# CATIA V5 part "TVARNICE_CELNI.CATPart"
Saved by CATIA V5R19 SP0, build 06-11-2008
Material "Steel": density 7860 kg/m3, Young's modulus 2e+11 Pa, Poisson ratio 0.266, thermal expansion 1.17e-05 1/K
Bounding box of the stored display mesh (mm): x -26 to 70, y -275 to 275, z 0 to 66
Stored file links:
  G:\UTB\Kombinované\Bakalářská práce\Catia\FORMA\TVARNICE_CELNI.CATPart
  G:\UTB\Kombinované\Bakalářská práce\Catia\KONCOVKA.CATPart
  D:\Aplikace\CATIA\Nová složka\win_b64\startup\materials\Catalog.CATMaterial
  G:\UTB\Kombinované\Bakalářská práce\Catia\FORMA_3.0_MODELY\installation space_HMT4.CATPart
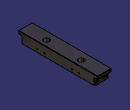
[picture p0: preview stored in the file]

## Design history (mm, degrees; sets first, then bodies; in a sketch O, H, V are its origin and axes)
Solid1: linked copy from another document
Sketch1 on xy-plane, origin (0, 0, 0), H (1, 0, 0), V (0, 1, 0)
  point P1 (22, 0)
  line L1 (-26, 275) -> (-26, -275)
  line L2 (-26, -275) -> (70, -275)
  line L3 (70, -275) -> (70, 275)
  line L4 (70, 275) -> (-26, 275)
  reference intersected line E1 through (0, 0) direction (-1, 0) from zx-plane
  reference intersected line E2 through (0, 0) direction (0, 1) from yz-plane
  distance L3 L1 = 96
  distance L4 L2 = 550
  distance L1 E2 = 26
  vertical: L1 V, L3 V
  horizontal: L2 H, L4 H
  equidistance: L1 L3 P1, L2 L4 P1
  coincidence: P1 E1
Pad1: profile Sketch1, direction (0, 0, 1), length 66
Set1 "ROZVODNE_KANALY"
  Sketch2 on xy-plane, origin (0, 0, 0), H (1, 0, 0), V (0, 1, 0)
    line L1 (30, 60) -> (0, 60)
    point P2 (0, 60)
    line L2 (30, 180) -> (0, 180)
    point P4 (0, 180)
    reference intersected line E1 through (0, 0) direction (0, 1) from yz-plane
    reference intersected line E2 through (0, 0) direction (0, 1) from yz-plane
    line L3 (30, 60) -> (30, 180)
    reference intersected line E3 through (0, 0) direction (-1, 0) from zx-plane
    reference intersected line E4 through (0, 120) direction (-1, 0) from Plane2
    reference intersected line E5 through (0, 0) direction (0, 1) from yz-plane
    distance L1 E3 = 60
    distance L3 E5 = 30
    horizontal: L1 H, L2 H
    coincidence: P2 E1, P4 E2
    vertical: L3 V
    symmetry: L2 L1 E4
  Plane1: type Offset, Offset 60, RefPlane Plane5
  Plane2: type Offset, Offset 60, RefPlane Plane5, reversed
  Plane3: type Offset, Offset 30, RefPlane yz-plane
  Plane4: type Offset, Offset 25, RefPlane Plane3
Body1 (main body)
  Sketch3 on yz-plane, origin (0, 0, 0), H (0, 1, 0), V (0, 0, 1)
    point P1 (275, 46)
    line L1 (275, 46) -> (255, 46)
    line L2 (255, 46) -> (255, 0)
    line L3 (255, 0) -> (275, 0)
    line L4 (275, 0) -> (275, 46)
    point P2 (255, 46)
    point P3 (255, 0)
    point P4 (275, 0)
    reference projected line E1 (-400, 0) -> (400, 0) from edge [start face of Pad1 | face of Pad1 from Sketch1.L3]
    reference projected line E2 (275, 0) -> (275, 116) from edge [face of Pad1 from Sketch1.L4 | face of Pad1 from Sketch1.L3]
    reference intersected line E3 through (0, 0) direction (0, 1) from zx-plane
    point P7 (-275, 46)
    point P8 (-255, 46)
    point P9 (-255, 0)
    point P10 (-275, 0)
    line L5 (-275, 46) -> (-255, 46)
    line L6 (-255, 46) -> (-255, 0)
    line L7 (-255, 0) -> (-275, 0)
    line L8 (-275, 0) -> (-275, 46)
    reference projected line E4 (-400, 66) -> (400, 66) from edge [face of Pad1 from Sketch1.L3 | end face of Pad1]
    distance L2 L4 = 20
    distance L1 E4 = 20
    horizontal: L1 H, L3 H
    vertical: L2 V, L4 V
    coincidence: L3 E1, L4 E2
    symmetry: P1 P7 E3, P2 P8 E3, P3 P9 E3, P4 P10 E3, L1 L5 E3, L2 L6 E3, L3 L7 E3, L4 L8 E3
  Pocket1: profile Sketch3, direction (-1, 0, 0), through (limit type 3), opposite side through (limit type 3)
  Body2
    RectPattern1: of Solid1, direction 1 instances 8, spacing 60, along Y axis reversed
    Symmetry1: Reference xy-plane, ToTransfor RectPattern1
  Remove1: tool Body2
  Trim1: faces to remove start face of Pad1 (x8)
  Chamfer1: length 5, angle 45, on edge [face of Pad1 from Sketch1.L3 | face of Pocket1 from Sketch3.L6]; edge [face of Pocket1 from Sketch3.L6 | face of Pad1 from Sketch1.L1]; edge [face of Pad1 from Sketch1.L1 | face of Pocket1 from Sketch3.L2]; edge [face of Pad1 from Sketch1.L3 | face of Pad1 from Sketch1.L2]; edge [face of Pad1 from Sketch1.L2 | face of Pad1 from Sketch1.L1]; edge [face of Pad1 from Sketch1.L1 | face of Pad1 from Sketch1.L4]; edge [face of Pad1 from Sketch1.L4 | face of Pad1 from Sketch1.L3]; edge [face of Pocket1 from Sketch3.L2 | face of Pad1 from Sketch1.L3]
  Chamfer2: length 2, angle 45, on end face of Pad1; edge [face of Pad1 from Sketch1.L3 | face of Pocket1 from Sketch3.L1]; edge [face of Pocket1 from Sketch3.L1 | face of Chamfer1] (x2); edge [face of Pocket1 from Sketch3.L1 | face of Pad1 from Sketch1.L4]; edge [face of Pad1 from Sketch1.L1 | face of Pocket1 from Sketch3.L1]; edge [face of Pad1 from Sketch1.L3 | face of Pocket1 from Sketch3.L5]; edge [face of Pocket1 from Sketch3.L5 | face of Chamfer1] (x2); edge [face of Pad1 from Sketch1.L2 | face of Pocket1 from Sketch3.L5]; edge [face of Pad1 from Sketch1.L1 | face of Pocket1 from Sketch3.L5]
  Plane5: type Offset, Offset 180, RefPlane zx-plane
  Sketch4 on yz-plane, origin (0, 0, 0), H (0, 1, 0), V (0, 0, 1)
    arc A1 centre (180, 3) radius 3 from (182.9886, 3.2615) to (177.0114, 3.2615) ccw
    point P1 (180, 3)
    line L1 (182.9886, 3.2615) -> (183.2739, 0)
    point P2 (183.2739, 0)
    line L2 (183.2739, 0) -> (176.7261, 0)
    point P3 (176.7261, 0)
    line L3 (176.7261, 0) -> (177.0114, 3.2615)
    reference intersected line E1 through (0, 0) direction (-1, 0) from xy-plane
    reference intersected line E2 through (180, 0) direction (0, 1) from Plane5
    reference intersected line E3 through (180, 0) direction (0, 1) from Plane5
    point P4 (177.0114, 3.2615)
    point P5 (182.9886, 3.2615)
    reference intersected line E4 through (240, 0) direction (0, 1) from Plane1
    point P9 (296.7261, 0)
    point P10 (303.2739, 0)
    point P11 (302.9886, 3.2615)
    point P12 (297.0114, 3.2615)
    arc A2 centre (300, 3) radius 3 from (297.0114, 3.2615) to (302.9886, 3.2615) cw
    line L4 (297.0114, 3.2615) -> (296.7261, 0)
    line L5 (296.7261, 0) -> (303.2739, 0)
    line L6 (303.2739, 0) -> (302.9886, 3.2615)
    reference intersected line E5 through (120, 0) direction (0, 1) from Plane2
    point P16 (56.7261, 0)
    point P17 (63.2739, 0)
    point P18 (62.9886, 3.2615)
    point P19 (57.0114, 3.2615)
    arc A3 centre (60, 3) radius 3 from (57.0114, 3.2615) to (62.9886, 3.2615) cw
    line L7 (57.0114, 3.2615) -> (56.7261, 0)
    line L8 (56.7261, 0) -> (63.2739, 0)
    line L9 (63.2739, 0) -> (62.9886, 3.2615)
    radius A1 = 3
    angle L1 L2 = 85
    horizontal: L2 H
    coincidence: L2 E1, P1 E3
    symmetry: L3 L1 E2, P2 P9 E4, P3 P10 E4, P4 P11 E4, P5 P12 E4, A1 A2 E4, L1 L4 E4, L2 L5 E4, L3 L6 E4, P2 P16 E5, P3 P17 E5, P4 P18 E5, P5 P19 E5, A1 A3 E5, L1 L7 E5, L2 L8 E5, L3 L9 E5
    tangency: A1 L3, A1 L1, A1 L2
  Pocket2: profile Sketch4, direction (1, 0, 0), length 30, opposite side length 3
  Sketch5 on Plane5, origin (0, 180, 0), H (-1, 0, 0), V (0, 0, 1)
    arc A1 centre (-30, 3) radius 3 from (-27.0114, 3.2615) to (-32.9886, 3.2615) ccw
    point P1 (-30, 3)
    reference intersected line E1 through (-30, 0) direction (0, -1) from Plane3
    reference intersected line E2 through (0, 0) direction (-1, 0) from xy-plane
    line L1 (-32.9886, 3.2615) -> (-33.2739, 0)
    line L2 (-33.2739, 0) -> (-26.7261, 0)
    line L3 (-26.7261, 0) -> (-27.0114, 3.2615)
    reference intersected line E3 through (0, 0) direction (-1, 0) from xy-plane
    reference intersected line E4 through (-30, 0) direction (0, -1) from Plane3
    radius A1 = 3
    angle L3 L2 = 85
    coincidence: P1 E1, L2 E3
    tangency: A1 E2, L3 A1, L1 A1
    horizontal: L2 H
    symmetry: L3 L1 E4
  Pocket3: profile Sketch5, direction (0, -1, 0), length 130, opposite side length 10
  Fillet1: radius 3, on edge [face of Pocket3 from Sketch5.A1 | end face of Pocket3]; edge [face of Pocket2 from Sketch4.A1 | start face of Pocket2]; edge [face of Pocket2 from Sketch4.A3 | start face of Pocket2]; edge [start face of Pocket3 | face of Pocket3 from Sketch5.A1]; edge [face of Pocket3 from Sketch5.A1 | face of Pocket2 from Sketch4.A3]; edge [face of Pocket3 from Sketch5.A1 | face of Pocket2 from Sketch4.A1]
  Intersect1: ToIntersect1 zx-plane, ToIntersect2 yz-plane
  Sketch6 on face of Pocket1 from Sketch3.L2, origin (54.5146, 255, 17.6418), H (1, 0, 0), V (0, 0, -1)
    point P1 (0.4854, -2.3582)
    reference projected line E1 (25.4854, 17.6418) -> (-134.5146, 17.6418) from edge [start face of Pad1 | face of Pocket1 from Sketch3.L2]
    reference projected line E2 (10.4854, 17.6418) -> (10.4854, -58.3582) from edge [face of Pocket1 from Sketch3.L2 | face of Chamfer1]
    distance P1 E1 = 20
    distance P1 E2 = 10
  Hole1: placed by Sketch6, at (55, 255, 20) direction (0, -1, 0), diameter 8, depth 160, V-bottom angle 120
  Sketch7 on face of Pad1 from Sketch1.L3, origin (70, 205.1332, 34.9028), H (0, 1, 0), V (0, 0, 1)
    point P1 (-110.1332, -14.9028)
    reference projected line E1 (49.8668, -34.9028) -> (49.8668, 41.0972) from edge [face of Pocket1 from Sketch3.L2 | face of Chamfer1]
    reference projected line E2 (-605.1332, -34.9028) -> (194.8668, -34.9028) from edge [start face of Pad1 | face of Pad1 from Sketch1.L3]
    distance P1 E1 = 160
    distance P1 E2 = 20
  Hole2: placed by Sketch7, at (70, 95, 20) direction (-1, 0, 0), diameter 8, depth 63, V-bottom angle 120
  Mirror1: of Hole2, about zx-plane
  Mirror2: of Hole1, about zx-plane
  Sketch8 on face of Pad1 from Sketch1.L1, origin (-26, -340.4239, 34.4779), H (0, 1, 0), V (0, 0, -1)
    point P1 (110.4239, 14.4779)
    reference projected line E1 (740.4239, 34.4779) -> (-59.5761, 34.4779) from edge [start face of Pad1 | face of Pad1 from Sketch1.L1]
    reference projected line E2 (85.4239, 34.4779) -> (85.4239, -41.5221) from edge [face of Pocket1 from Sketch3.L6 | face of Chamfer1]
    distance P1 E1 = 20
    distance P1 E2 = 25
  Hole3: placed by Sketch8, at (-26, -230, 20) direction (1, 0, 0), diameter 8, depth 81, V-bottom angle 120
  Sketch9 on face of Pocket1 from Sketch3.L2, origin (0.6599, 255, 20.6303), H (1, 0, 0), V (0, 0, 1)
    point P1 (6.3401, -0.6303)
    reference projected line E1 (69.3401, -20.6303) -> (69.3401, 55.3697) from edge [face of Pad1 from Sketch1.L3 | face of Chamfer1]
    reference projected line E2 (79.3401, -20.6303) -> (-80.6599, -20.6303) from edge [face of Pocket1 from Sketch3.L6 | start face of Pad1]
    distance P1 E1 = 63
    distance P1 E2 = 20
  Hole4: placed by Sketch9, at (7, 255, 20) direction (0, -1, 0), diameter 8, through (limit type 3)
  Mirror3: of Hole3, about zx-plane
  Sketch10 on face of Pocket1 from Sketch3.L6, origin (-48.4988, -255, 26.5459), H (1, 0, 0), V (0, 0, 1)
    point P1 (37.4988, -6.5459)
    reference projected line E1 (128.4988, -26.5459) -> (-31.5012, -26.5459) from edge [face of Pocket1 from Sketch3.L6 | start face of Pad1]
    reference intersected line E2 through (48.4988, 0) direction (0, 1) from yz-plane
    distance P1 E1 = 20
    distance P1 E2 = 11
  Hole5: placed by Sketch10, at (-11, -255, 20) direction (0, 1, 0), diameter 8, through (limit type 3)
  Sketch11 on face of Pocket1 from Sketch3.L2, origin (0, 255, 0), H (1, 0, 0), V (0, 0, 1)
    circle A1 centre (-11, 20) radius 5.1
    point P1 (-11, 20)
    circle A2 centre (-11, 20) radius 7
    point P2 (-11, 20)
    circle A3 centre (55, 20) radius 5.1
    point P3 (55, 20)
    circle A4 centre (55, 20) radius 7
    point P4 (55, 20)
    reference projected circle E1 centre (-11, 20) radius 4 from edge [face of Pocket1 from Sketch3.L6 | face of Hole5]
    reference projected circle E2 centre (-11, 20) radius 4 from edge [face of Pocket1 from Sketch3.L6 | face of Hole5]
    reference projected circle E3 centre (55, 20) radius 4 from edge [face of Pocket1 from Sketch3.L6 | face of Mirror2]
    reference projected circle E4 centre (55, 20) radius 4 from edge [face of Pocket1 from Sketch3.L6 | face of Mirror2]
    radius A1 = 5.1
    radius A2 = 7
    radius A3 = 5.1
    radius A4 = 7
    concentricity: P2 E1, P1 E2, P4 E3, P3 E4
  Pocket4: profile Sketch11, direction (0, -1, 0), length 1.2
  Mirror4: of Pocket4, about zx-plane
  Sketch12 on face of Pocket1 from Sketch3.L6, origin (0, -255, 0), H (-1, 0, 0), V (0, 0, 1)
    point P1 (11, 20)
    point P2 (-55, 20)
    reference projected circle E1 centre (-55, 20) radius 4 from edge [face of Pocket1 from Sketch3.L6 | face of Mirror2]
    reference projected circle E2 centre (11, 20) radius 4 from edge [face of Pocket1 from Sketch3.L6 | face of Hole5]
    point P3 (-7, 20)
    reference projected circle E3 centre (-7, 20) radius 4 from edge [face of Hole4 | face of Pocket1 from Sketch3.L2]
    concentricity: P2 E1, P1 E2, P3 E3
  Sketch13 on face of Pocket1 from Sketch3.L6, origin (62, -255, 20), H (1, 0, 0), V (0, 0, 1)
    point P1 (-7, 0)
    reference projected point E1 (-7, 0) from Sketch12.P2
    coincidence: E1 P1
  Hole6: placed by Sketch13, at (55, -255, 20) direction (0, 1, 0), diameter 9, depth 10, V-bottom angle 120
  UserPattern1: of Hole6, copies 3, at the points of Sketch12
  Sketch14 on face of Pocket1 from Sketch3.L2, origin (0, 255, 0), H (1, 0, 0), V (0, 0, 1)
    point P1 (55, 20)
    point P2 (7, 20)
    point P3 (-11, 20)
    reference projected circle E1 centre (-11, 20) radius 4 from edge [face of Hole5 | face of Pocket1 from Sketch3.L2]
    reference projected circle E2 centre (7, 20) radius 4 from edge [face of Hole4 | face of Pocket1 from Sketch3.L2]
    reference projected circle E3 centre (55, 20) radius 4 from edge [face of Hole1 | face of Pocket1 from Sketch3.L2]
    concentricity: P3 E1, P2 E2, P1 E3
  Sketch15 on face of Pocket1 from Sketch3.L2, origin (-44, 255, 20), H (1, 0, 0), V (0, 0, -1)
    point P1 (33, 0)
    reference projected point E1 (33, 0) from Sketch14.P3
    coincidence: E1 P1
  Hole7: placed by Sketch15, at (-11, 255, 20) direction (0, -1, 0), diameter 9, depth 10, V-bottom angle 120
  UserPattern2: of Hole7, copies 3, at the points of Sketch14
  Sketch16 on face of Pad1 from Sketch1.L3, origin (70, 0, 0), H (0, 1, 0), V (0, 0, 1)
    point P1 (-95, 20)
    point P2 (95, 20)
    reference projected circle E1 centre (95, 20) radius 4 from edge [face of Pad1 from Sketch1.L3 | face of Hole2]
    reference projected circle E2 centre (-95, 20) radius 4 from edge [face of Pad1 from Sketch1.L3 | face of Mirror1]
    point P3 (-145, 20)
    reference intersected line E3 through (0, 0) direction (-1, 0) from xy-plane
    distance P3 P2 = 240
    distance P3 E3 = 20
    concentricity: P2 E1, P1 E2
  Sketch17 on face of Pad1 from Sketch1.L3, origin (70, 208, 20), H (0, 1, 0), V (0, 0, 1)
    point P1 (-113, 0)
    reference projected point E1 (-113, 0) from Sketch16.P2
    coincidence: E1 P1
  Hole8: placed by Sketch17, at (70, 95, 20) direction (-1, 0, 0), diameter 9, depth 10, V-bottom angle 120
  UserPattern3: of Hole8, copies 3, at the points of Sketch16
  Sketch18 on face of Pad1 from Sketch1.L1, origin (-26, 0, 0), H (0, -1, 0), V (0, 0, 1)
    point P1 (-230, 20)
    point P2 (230, 20)
    reference projected circle E1 centre (230, 20) radius 4 from edge [face of Pad1 from Sketch1.L1 | face of Hole3]
    reference projected circle E2 centre (-230, 20) radius 4 from edge [face of Pad1 from Sketch1.L1 | face of Mirror3]
    concentricity: P2 E1, P1 E2
  Sketch19 on face of Pad1 from Sketch1.L1, origin (-26, 350, 20), H (0, 1, 0), V (0, 0, -1)
    point P1 (-120, 0)
    reference projected point E1 (-120, 0) from Sketch18.P1
    coincidence: E1 P1
  Hole9: placed by Sketch19, at (-26, 230, 20) direction (1, 0, 0), diameter 9, depth 10, V-bottom angle 120
  UserPattern4: of Hole9, copies 2, at the points of Sketch18
  Mirror5: of Pocket2, Pocket3, about zx-plane
  Fillet2: radius 3, on edge [face of Mirror5 | face of Mirror5] (x6)
  Body3 "installation space_HMT4"
    Solid2: solid without history
  Remove2: tool Body3
  Body4 "installation space_HMT4"
    Solid3: solid without history
  Remove3: tool Body4
  RectPattern2: of Hole2, Hole8, direction 1 instances 2, spacing 50, along Y axis
  Sketch20 on face of Pad1 from Sketch1.L3, origin (70, -144.7564, 19.6627), H (0, 1, 0), V (0, 0, 1)
    point P1 (-0.2436, 0.3373)
    reference projected circle E1 centre (-0.2436, 0.3373) radius 4.5 from edge [face of Pad1 from Sketch1.L3 | face of UserPattern3]
    concentricity: P1 E1
  Hole10: placed by Sketch20, at (70, -145, 20) direction (-1, 0, 0), diameter 8, depth 63, V-bottom angle 120
  Sketch21 on xy-plane, origin (0, 0, 0), H (1, 0, 0), V (0, 1, 0)
    circle A1 centre (30, 120) radius 0.75
    point P1 (30, 120)
    reference projected arc E1 centre (30, 120) radius 18.5 from (48.5, 120) to (11.5, 120) ccw from edge [end face of Pad1 | face of Solid2]
    reference intersected line E2 through (0, 0) direction (-1, 0) from zx-plane
    circle A2 centre (30, -120) radius 0.75
    radius A1 = 0.75
    concentricity: P1 E1
    symmetry: A1 A2 E2
  Pocket5: profile Sketch21, direction (0, 0, 1), length 10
